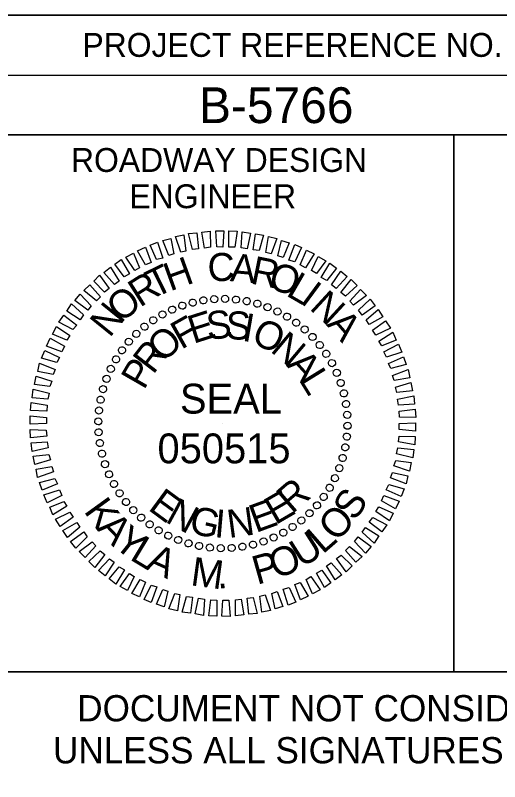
# Model space of a CAD drawing. Extents: x 573078 to 573131.9, y -55221.3 to -55195.5.
# Drawn here: x 573107.676 to 573109.706, y -55203.009 to -55199.798 of the extents above; entities that cross this region are included whole.
import ezdxf

# ---------------------------------------------------------------- set-up
doc = ezdxf.new("R2010")
doc.units = 0
for name, color, linetype in [('Prop Dimension', 7, 'Continuous'), ('Scratch_Level_1', 7, 'Continuous'), ('Sheet Data Field CELL', 7, 'Continuous'), ('Sheet Profile CELL', 7, 'Continuous'), ('Sheet Sticker Exception Certification CELL', 7, 'Continuous')]:
    doc.layers.add(name, color=color, linetype=linetype)

msp = doc.modelspace()

# ---------------------------------------------------------------- linework, layer by layer
at = {"layer": 'Prop Dimension'}
for p, q in [((573108.3752, -55201.0139), (573108.3752, -55201.0139)), ((573108.419, -55201.0014), (573108.419, -55201.0014)), ((573108.4648, -55200.9931), (573108.4648, -55200.9931)), ((573108.5094, -55200.9869), (573108.5094, -55200.9869)), ((573108.5553, -55200.9859), (573108.5553, -55200.9859)), ((573108.6011, -55200.9889), (573108.6011, -55200.9889)), ((573108.646, -55200.9964), (573108.646, -55200.9964)), ((573108.6897, -55201.0056), (573108.6897, -55201.0056)), ((573108.3336, -55201.0306), (573108.3336, -55201.0306)), ((573108.7335, -55201.0202), (573108.7335, -55201.0202)), ((573108.7751, -55201.0389), (573108.7751, -55201.0389)), ((573108.2533, -55201.0755), (573108.2533, -55201.0755)), ((573108.2928, -55201.0514), (573108.2928, -55201.0514)), ((573108.8156, -55201.0598), (573108.8156, -55201.0598)), ((573108.2169, -55201.1014), (573108.2169, -55201.1014)), ((573108.8531, -55201.0859), (573108.8531, -55201.0859)), ((573108.1825, -55201.1327), (573108.1825, -55201.1327)), ((573108.8897, -55201.1139), (573108.8897, -55201.1139)), ((573108.1512, -55201.1651), (573108.1512, -55201.1651)), ((573108.9218, -55201.1452), (573108.9218, -55201.1452)), ((573108.1232, -55201.2014), (573108.1232, -55201.2014)), ((573108.9531, -55201.1796), (573108.9531, -55201.1796)), ((573108.0971, -55201.2389), (573108.0971, -55201.2389)), ((573108.9792, -55201.216), (573108.9792, -55201.216)), ((573109.0031, -55201.2555), (573109.0031, -55201.2555)), ((573108.0762, -55201.2796), (573108.0762, -55201.2796)), ((573109.0239, -55201.2963), (573109.0239, -55201.2963)), ((573108.0575, -55201.3213), (573108.0575, -55201.3213)), ((573108.0429, -55201.365), (573108.0429, -55201.365)), ((573109.0405, -55201.3379), (573109.0405, -55201.3379)), ((573109.053, -55201.3817), (573109.053, -55201.3817)), ((573108.0337, -55201.4087), (573108.0337, -55201.4087)), ((573109.0614, -55201.4275), (573109.0614, -55201.4275)), ((573108.0262, -55201.4534), (573108.0262, -55201.4534)), ((573109.0676, -55201.4721), (573109.0676, -55201.4721)), ((573108.0232, -55201.4992), (573108.0232, -55201.4992)), ((573108.546, -55201.5087), (573108.546, -55201.5087)), ((573109.0688, -55201.518), (573109.0688, -55201.518)), ((573108.0242, -55201.545), (573108.0242, -55201.545)), ((573108.0304, -55201.5899), (573108.0304, -55201.5899)), ((573109.0655, -55201.5638), (573109.0655, -55201.5638)), ((573109.0584, -55201.6087), (573109.0584, -55201.6087)), ((573108.0387, -55201.6358), (573108.0387, -55201.6358)), ((573109.0489, -55201.6524), (573109.0489, -55201.6524)), ((573108.0512, -55201.6795), (573108.0512, -55201.6795)), ((573108.0679, -55201.7211), (573108.0679, -55201.7211)), ((573109.0343, -55201.6962), (573109.0343, -55201.6962)), ((573109.0156, -55201.7378), (573109.0156, -55201.7378)), ((573108.0887, -55201.7616), (573108.0887, -55201.7616)), ((573108.9947, -55201.7783), (573108.9947, -55201.7783)), ((573108.1128, -55201.8012), (573108.1128, -55201.8012)), ((573108.9688, -55201.8158), (573108.9688, -55201.8158)), ((573108.1387, -55201.8378), (573108.1387, -55201.8378)), ((573108.17, -55201.872), (573108.17, -55201.872)), ((573108.9406, -55201.8524), (573108.9406, -55201.8524)), ((573108.2024, -55201.9033), (573108.2024, -55201.9033)), ((573108.9093, -55201.8845), (573108.9093, -55201.8845)), ((573108.2387, -55201.9315), (573108.2387, -55201.9315)), ((573108.8385, -55201.9419), (573108.8385, -55201.9419)), ((573108.8751, -55201.9158), (573108.8751, -55201.9158)), ((573108.2762, -55201.9574), (573108.2762, -55201.9574)), ((573108.3169, -55201.9783), (573108.3169, -55201.9783)), ((573108.7989, -55201.9658), (573108.7989, -55201.9658)), ((573108.3586, -55201.997), (573108.3586, -55201.997)), ((573108.7168, -55202.0032), (573108.7168, -55202.0032)), ((573108.7584, -55201.9866), (573108.7584, -55201.9866)), ((573108.4023, -55202.0116), (573108.4023, -55202.0116)), ((573108.446, -55202.0211), (573108.446, -55202.0211)), ((573108.4907, -55202.0282), (573108.4907, -55202.0282)), ((573108.5365, -55202.0315), (573108.5365, -55202.0315)), ((573108.5823, -55202.0303), (573108.5823, -55202.0303)), ((573108.6272, -55202.0241), (573108.6272, -55202.0241)), ((573108.6731, -55202.0157), (573108.6731, -55202.0157))]:
    msp.add_line(p, q, dxfattribs=at)
for points in [[(573108.369, -55200.7911), (573108.347, -55200.7256), (573108.3824, -55200.7182), (573108.3907, -55200.786)], [(573108.419, -55200.7797), (573108.4023, -55200.7131), (573108.4365, -55200.7099), (573108.444, -55200.7765)], [(573108.4689, -55200.7735), (573108.4574, -55200.7068), (573108.4928, -55200.7027), (573108.4939, -55200.7703)], [(573108.521, -55200.7682), (573108.5157, -55200.7006), (573108.5502, -55200.7015), (573108.546, -55200.7693)], [(573108.571, -55200.7693), (573108.571, -55200.7015), (573108.6053, -55200.7027), (573108.596, -55200.7703)], [(573108.6231, -55200.7723), (573108.6272, -55200.7048), (573108.6615, -55200.711), (573108.6481, -55200.7765)], [(573108.6731, -55200.7807), (573108.6823, -55200.714), (573108.7168, -55200.7193), (573108.6981, -55200.7839)], [(573108.7261, -55200.7922), (573108.7365, -55200.7244), (573108.7719, -55200.7328), (573108.748, -55200.7973)], [(573108.2678, -55200.8214), (573108.2408, -55200.761), (573108.272, -55200.7485), (573108.294, -55200.8152)], [(573108.319, -55200.8047), (573108.2949, -55200.7423), (573108.3273, -55200.7328), (573108.3407, -55200.7973)], [(573108.776, -55200.8057), (573108.7918, -55200.7411), (573108.8239, -55200.7515), (573108.798, -55200.8131)], [(573108.823, -55200.8244), (573108.8468, -55200.7589), (573108.876, -55200.7714), (573108.8469, -55200.8318)], [(573108.222, -55200.8432), (573108.1887, -55200.7848), (573108.2211, -55200.7703), (573108.2449, -55200.8339)], [(573108.8698, -55200.8443), (573108.8959, -55200.7828), (573108.9281, -55200.7973), (573108.8927, -55200.8557)], [(573108.1315, -55200.8943), (573108.0929, -55200.8411), (573108.12, -55200.8214), (573108.1544, -55200.8818)], [(573108.1774, -55200.8681), (573108.1387, -55200.8119), (573108.1711, -55200.7953), (573108.197, -55200.8557)], [(573108.9177, -55200.8681), (573108.9459, -55200.8089), (573108.9771, -55200.8265), (573108.9376, -55200.8806)], [(573108.092, -55200.9255), (573108.0471, -55200.8756), (573108.0753, -55200.8536), (573108.1116, -55200.9119)], [(573108.9584, -55200.8964), (573108.9947, -55200.836), (573109.0218, -55200.8577), (573108.9813, -55200.9089)], [(573108.0503, -55200.9577), (573108.0045, -55200.9119), (573108.0295, -55200.8869), (573108.07, -55200.9431)], [(573109.001, -55200.9276), (573109.0396, -55200.8702), (573109.0667, -55200.8931), (573109.0209, -55200.9422)], [(573109.0405, -55200.9598), (573109.0834, -55200.9056), (573109.1084, -55200.9306), (573109.0604, -55200.9755)], [(573108.0158, -55200.9943), (573107.9628, -55200.9515), (573107.9888, -55200.9276), (573108.0325, -55200.9776)], [(573109.078, -55200.9964), (573109.1229, -55200.9473), (573109.1479, -55200.9723), (573109.0938, -55201.013)], [(573107.9795, -55201.0338), (573107.9253, -55200.9931), (573107.9483, -55200.966), (573107.9941, -55201.0151)], [(573107.9483, -55201.0734), (573107.892, -55201.038), (573107.9117, -55201.0077), (573107.9617, -55201.0535)], [(573109.1146, -55201.0338), (573109.1625, -55200.9869), (573109.1843, -55201.0151), (573109.1292, -55201.0547)], [(573109.1458, -55201.0743), (573109.1968, -55201.0306), (573109.2167, -55201.0609), (573109.1583, -55201.0942)], [(573107.917, -55201.1151), (573107.8587, -55201.0838), (573107.8795, -55201.0547), (573107.9337, -55201.0963)], [(573109.1729, -55201.1172), (573109.228, -55201.0776), (573109.2479, -55201.1088), (573109.1875, -55201.138)], [(573107.892, -55201.1597), (573107.8325, -55201.1338), (573107.8483, -55201.1014), (573107.9045, -55201.1401)], [(573109.2, -55201.163), (573109.2583, -55201.1264), (573109.2717, -55201.1588), (573109.2125, -55201.1826)], [(573107.8712, -55201.2076), (573107.8066, -55201.1838), (573107.8221, -55201.1514), (573107.8816, -55201.1847)], [(573109.2208, -55201.2076), (573109.2821, -55201.1764), (573109.2958, -55201.2097), (573109.2312, -55201.2305)], [(573107.8504, -55201.2535), (573107.7858, -55201.2347), (573107.7992, -55201.2025), (573107.8617, -55201.2317)], [(573109.2396, -55201.2567), (573109.303, -55201.2296), (573109.3145, -55201.2618), (573109.25, -55201.2784)], [(573107.8346, -55201.3034), (573107.7701, -55201.29), (573107.7775, -55201.2555), (573107.843, -55201.2817)], [(573109.2562, -55201.3067), (573109.3229, -55201.2826), (573109.3291, -55201.3171), (573109.2634, -55201.3284)], [(573107.8212, -55201.3534), (573107.7566, -55201.3451), (573107.7638, -55201.3097), (573107.8295, -55201.3317)], [(573109.2687, -55201.3567), (573109.3342, -55201.3368), (573109.3405, -55201.3722), (573109.275, -55201.3784)], [(573107.8129, -55201.4067), (573107.7462, -55201.4004), (573107.7504, -55201.365), (573107.818, -55201.3817)], [(573109.278, -55201.4067), (573109.3458, -55201.3921), (573109.3488, -55201.4275), (573109.2821, -55201.4316)], [(573107.8076, -55201.4566), (573107.74, -55201.4546), (573107.7421, -55201.4201), (573107.8096, -55201.4316)], [(573109.2842, -55201.4566), (573109.352, -55201.4483), (573109.3541, -55201.4837), (573109.2863, -55201.4816)], [(573107.8066, -55201.5087), (573107.7388, -55201.5117), (573107.7388, -55201.4763), (573107.8066, -55201.4837)], [(573109.2854, -55201.5087), (573109.353, -55201.5055), (573109.353, -55201.5409), (573109.2854, -55201.5337)], [(573107.8076, -55201.5608), (573107.74, -55201.5691), (573107.7379, -55201.5337), (573107.8055, -55201.5358)], [(573109.2842, -55201.5608), (573109.352, -55201.5629), (573109.35, -55201.5971), (573109.2821, -55201.5858)], [(573107.8138, -55201.6108), (573107.7462, -55201.6253), (573107.743, -55201.5899), (573107.8096, -55201.5858)], [(573109.2791, -55201.6108), (573109.3458, -55201.617), (573109.3416, -55201.6524), (573109.2738, -55201.6358)], [(573107.8233, -55201.6607), (573107.7576, -55201.6804), (573107.7513, -55201.645), (573107.817, -55201.6388)], [(573107.8358, -55201.7107), (573107.7691, -55201.7346), (573107.7629, -55201.7003), (573107.8284, -55201.6888)], [(573109.2708, -55201.6638), (573109.3354, -55201.6721), (573109.328, -55201.7075), (573109.2625, -55201.6857)], [(573109.2572, -55201.7137), (573109.3217, -55201.7274), (573109.3145, -55201.7616), (573109.2488, -55201.7357)], [(573107.8524, -55201.7607), (573107.7888, -55201.7878), (573107.7775, -55201.7554), (573107.842, -55201.7387)], [(573109.2416, -55201.7637), (573109.3062, -55201.7825), (573109.2926, -55201.8149), (573109.2301, -55201.7857)], [(573107.8712, -55201.8096), (573107.8096, -55201.8408), (573107.7962, -55201.8075), (573107.8608, -55201.7866)], [(573109.2208, -55201.8095), (573109.2854, -55201.8336), (573109.2696, -55201.8658), (573109.2104, -55201.8325)], [(573107.892, -55201.8544), (573107.8337, -55201.8908), (573107.8201, -55201.8586), (573107.8795, -55201.8345)], [(573107.9191, -55201.9003), (573107.8638, -55201.9398), (573107.8441, -55201.9086), (573107.9045, -55201.8794)], [(573109.2, -55201.8575), (573109.2592, -55201.8836), (573109.2437, -55201.9158), (573109.1875, -55201.8774)], [(573109.175, -55201.9023), (573109.2333, -55201.9336), (573109.2125, -55201.9628), (573109.1583, -55201.9211)], [(573107.9462, -55201.9428), (573107.895, -55201.9866), (573107.8754, -55201.9565), (573107.9337, -55201.9232)], [(573109.1438, -55201.944), (573109.2, -55201.9794), (573109.1801, -55202.0095), (573109.1301, -55201.9637)], [(573107.9774, -55201.9836), (573107.9295, -55202.0303), (573107.9075, -55202.0023), (573107.9628, -55201.9628)], [(573108.0137, -55202.0211), (573107.9691, -55202.0699), (573107.9441, -55202.0449), (573107.9982, -55202.0044)], [(573109.1125, -55201.9836), (573109.1667, -55202.0241), (573109.1438, -55202.0512), (573109.0979, -55202.0023)], [(573108.0512, -55202.0574), (573108.0087, -55202.1116), (573107.9837, -55202.0866), (573108.0316, -55202.0419)], [(573109.076, -55202.0231), (573109.1292, -55202.0657), (573109.103, -55202.0898), (573109.0593, -55202.0398)], [(573108.0908, -55202.0898), (573108.0524, -55202.147), (573108.0253, -55202.124), (573108.0711, -55202.0752)], [(573109.0417, -55202.0595), (573109.0875, -55202.1053), (573109.0625, -55202.1303), (573109.0218, -55202.0741)], [(573109.0001, -55202.0919), (573109.0447, -55202.1419), (573109.0167, -55202.1636), (573108.9801, -55202.1053)], [(573108.1336, -55202.121), (573108.0971, -55202.1814), (573108.07, -55202.1595), (573108.1107, -55202.1085)], [(573108.1741, -55202.149), (573108.1461, -55202.2085), (573108.1149, -55202.1907), (573108.1544, -55202.1365)], [(573108.9605, -55202.1231), (573108.9989, -55202.1761), (573108.9718, -55202.196), (573108.9376, -55202.1356)], [(573108.222, -55202.1731), (573108.1961, -55202.2344), (573108.1637, -55202.2199), (573108.1991, -55202.1615)], [(573108.9147, -55202.149), (573108.9531, -55202.2053), (573108.9209, -55202.2219), (573108.8948, -55202.1615)], [(573108.269, -55202.1928), (573108.2449, -55202.2585), (573108.2158, -55202.246), (573108.2449, -55202.1856)], [(573108.8239, -55202.196), (573108.851, -55202.2564), (573108.8198, -55202.2689), (573108.798, -55202.2023)], [(573108.8698, -55202.174), (573108.9031, -55202.2323), (573108.8709, -55202.2469), (573108.8468, -55202.1835)], [(573108.3158, -55202.2115), (573108.3002, -55202.2761), (573108.2678, -55202.2657), (573108.294, -55202.2044)], [(573108.3657, -55202.2252), (573108.3553, -55202.2927), (573108.3199, -55202.2844), (573108.344, -55202.2199)], [(573108.419, -55202.2365), (573108.4095, -55202.3032), (573108.3752, -55202.2981), (573108.394, -55202.2335)], [(573108.723, -55202.2261), (573108.7448, -55202.2918), (573108.7094, -55202.299), (573108.7011, -55202.2314)], [(573108.773, -55202.2127), (573108.7969, -55202.2752), (573108.7647, -55202.2844), (573108.751, -55202.2199)], [(573108.4689, -55202.2448), (573108.4648, -55202.3127), (573108.4303, -55202.3064), (573108.444, -55202.2407)], [(573108.521, -55202.2481), (573108.521, -55202.3157), (573108.4865, -55202.3147), (573108.496, -55202.2469)], [(573108.571, -55202.249), (573108.5761, -55202.3168), (573108.5418, -55202.3157), (573108.546, -55202.2481)], [(573108.6231, -55202.2439), (573108.6344, -55202.3106), (573108.599, -55202.3147), (573108.5981, -55202.2469)], [(573108.6731, -55202.2377), (573108.6897, -55202.3043), (573108.6552, -55202.3073), (573108.6481, -55202.2407)]]:
    msp.add_lwpolyline(points, close=True, dxfattribs=at)
for centre, major_axis in [((573108.4643, -55200.9927), (-0.0023, 0.0148)), ((573108.5096, -55200.9876), (-0.001, 0.015)), ((573108.5551, -55200.9864), (0.0003, 0.015)), ((573108.6006, -55200.9892), (0.0016, 0.0149)), ((573108.6457, -55200.9959), (0.0029, 0.0147)), ((573108.3336, -55201.0315), (-0.0061, 0.0137)), ((573108.376, -55201.0147), (-0.0049, 0.0142)), ((573108.4196, -55201.0018), (-0.0036, 0.0146)), ((573108.69, -55201.0065), (0.0041, 0.0144)), ((573108.7332, -55201.021), (0.0054, 0.014)), ((573108.2928, -55201.0518), (-0.0073, 0.0131)), ((573108.775, -55201.0392), (0.0066, 0.0135)), ((573108.8151, -55201.0609), (0.0077, 0.0129)), ((573108.2539, -55201.0756), (-0.0084, 0.0124)), ((573108.8531, -55201.0861), (0.0088, 0.0121)), ((573108.2173, -55201.1027), (-0.0094, 0.0117)), ((573108.8887, -55201.1144), (0.0098, 0.0113)), ((573108.1832, -55201.1329), (-0.0104, 0.0108)), ((573108.9218, -55201.1458), (0.0108, 0.0104)), ((573108.1518, -55201.1659), (-0.0113, 0.0098)), ((573108.952, -55201.1799), (0.0117, 0.0094)), ((573108.1234, -55201.2016), (-0.0121, 0.0088)), ((573108.9791, -55201.2165), (0.0124, 0.0084)), ((573108.0983, -55201.2396), (-0.0129, 0.0077)), ((573109.0029, -55201.2554), (0.0131, 0.0073)), ((573108.0765, -55201.2797), (-0.0135, 0.0066)), ((573108.0584, -55201.3214), (-0.014, 0.0054)), ((573109.0232, -55201.2962), (0.0137, 0.0061)), ((573109.0399, -55201.3386), (0.0142, 0.0049)), ((573108.0439, -55201.3647), (-0.0144, 0.0041)), ((573109.0529, -55201.3823), (0.0146, 0.0036)), ((573108.0333, -55201.409), (-0.0147, 0.0029)), ((573109.0619, -55201.4269), (0.0148, 0.0023)), ((573108.0265, -55201.454), (-0.0149, 0.0016)), ((573109.0671, -55201.4722), (0.015, 0.001)), ((573108.0237, -55201.4995), (-0.015, 0.0003)), ((573108.0249, -55201.5451), (-0.015, -0.001)), ((573109.0683, -55201.5178), (0.015, -0.0003)), ((573109.0655, -55201.5632), (0.0149, -0.0016)), ((573108.0301, -55201.5904), (-0.0148, -0.0023)), ((573109.0588, -55201.6083), (0.0147, -0.0029)), ((573108.0392, -55201.635), (-0.0146, -0.0036)), ((573109.0481, -55201.6526), (0.0144, -0.0041)), ((573108.0521, -55201.6787), (-0.0142, -0.0049)), ((573109.0337, -55201.6958), (0.014, -0.0054)), ((573108.0688, -55201.7211), (-0.0137, -0.0061)), ((573109.0155, -55201.7376), (0.0135, -0.0066)), ((573108.0892, -55201.7619), (-0.0131, -0.0073)), ((573108.113, -55201.8007), (-0.0124, -0.0084)), ((573108.9938, -55201.7777), (0.0129, -0.0077)), ((573108.9686, -55201.8157), (0.0121, -0.0088)), ((573108.1401, -55201.8374), (-0.0117, -0.0094)), ((573108.9402, -55201.8513), (0.0113, -0.0098)), ((573108.1703, -55201.8715), (-0.0108, -0.0104)), ((573108.9089, -55201.8844), (0.0104, -0.0108)), ((573108.2033, -55201.9029), (-0.0098, -0.0113)), ((573108.239, -55201.9312), (-0.0088, -0.0121)), ((573108.8747, -55201.9146), (0.0094, -0.0117)), ((573108.277, -55201.9564), (-0.0077, -0.0129)), ((573108.8381, -55201.9417), (0.0084, -0.0124)), ((573108.317, -55201.9781), (-0.0066, -0.0135)), ((573108.7585, -55201.9858), (0.0061, -0.0137)), ((573108.7993, -55201.9655), (0.0073, -0.0131)), ((573108.3588, -55201.9963), (-0.0054, -0.014)), ((573108.402, -55202.0108), (-0.0041, -0.0144)), ((573108.4463, -55202.0214), (-0.0029, -0.0147)), ((573108.6277, -55202.0246), (0.0023, -0.0148)), ((573108.6724, -55202.0155), (0.0036, -0.0146)), ((573108.7161, -55202.0025), (0.0049, -0.0142)), ((573108.4914, -55202.0281), (-0.0016, -0.0149)), ((573108.5369, -55202.0309), (-0.0003, -0.015)), ((573108.5825, -55202.0297), (0.001, -0.015))]:
    msp.add_ellipse(centre, major_axis=major_axis, ratio=0.999708, dxfattribs=at)
at = {"layer": 'Scratch_Level_1'}
msp.add_line((573108.546, -55201.5087), (573108.546, -55201.5087), dxfattribs=at)
at = {"layer": 'Sheet Profile CELL'}
for p, q in [((573107.5142, -55200.0494), (573111.5142, -55200.0494)), ((573109.5142, -55200.2994), (573109.5142, -55202.5484))]:
    msp.add_line(p, q, dxfattribs=at)
for points in [[(573111.5142, -55199.7984), (573081.5142, -55199.7984), (573081.5142, -55220.7984), (573111.5142, -55220.7984)], [(573107.5142, -55199.7984), (573111.5142, -55199.7984), (573111.5142, -55200.2994), (573107.5142, -55200.2994)], [(573107.5142, -55200.2994), (573109.5142, -55200.2994), (573109.5142, -55202.5494), (573107.5142, -55202.5494)], [(573109.5142, -55200.2994), (573111.5142, -55200.2994), (573111.5142, -55202.5494), (573109.5142, -55202.5494)]]:
    msp.add_lwpolyline(points, close=True, dxfattribs=at)
at = {"layer": 'Sheet Sticker Exception Certification CELL'}
msp.add_line((573107.5142, -55202.5494), (573111.5149, -55202.5494), dxfattribs=at)

# ---------------------------------------------------------------- texts
at = {"layer": 'Prop Dimension'}
for s, height, rotation, p in [('H', 0.1177, 19.8207, (573108.3243, -55200.9554)), ('C', 0.1177, 1.0718, (573108.4826, -55200.9128)), ('A', 0.1177, 354.8222, (573108.5742, -55200.9117)), ('R', 0.1177, 348.5725, (573108.6576, -55200.9211)), ('T', 0.1177, 26.0703, (573108.2609, -55200.9846)), ('O', 0.1177, 342.3229, (573108.7304, -55200.9399)), ('R', 0.1177, 32.3199, (573108.1984, -55201.0241)), ('L', 0.1177, 329.8237, (573108.8066, -55200.97)), ('I', 0.1177, 323.5741, (573108.8649, -55201.0003)), ('O', 0.1177, 38.5695, (573108.1181, -55201.0898)), ('N', 0.1177, 317.3244, (573108.9054, -55201.0274)), ('N', 0.1177, 51.0688, (573108.0714, -55201.1523)), ('E', 0.1177, 17.6709, (573108.4222, -55201.1752)), ('S', 0.1177, 6.1833, (573108.4826, -55201.1586)), ('S', 0.1177, 358.4778, (573108.5567, -55201.1553)), ('I', 0.1177, 350.0931, (573108.6233, -55201.1607)), ('F', 0.1177, 29.3, (573108.3713, -55201.2002)), ('O', 0.1177, 335.3611, (573108.6596, -55201.1678)), ('A', 0.1177, 311.0748, (573108.9774, -55201.0949)), ('O', 0.1177, 43.5875, (573108.2972, -55201.2565)), ('N', 0.1177, 319.95, (573108.7409, -55201.2044)), ('R', 0.1177, 52.4166, (573108.2535, -55201.3065)), ('P', 0.1177, 60.1222, (573108.2151, -55201.371)), ('A', 0.1177, 312.2445, (573108.8096, -55201.2657)), ('L', 0.1177, 301.6752, (573108.8617, -55201.324)), ('SEAL', 0.12497, 360, (573108.366, -55201.4668)), ('050515', 0.12497, 360, (573108.2719, -55201.6751)), ('R', 0.1177, 40.7353, (573108.8357, -55201.8896)), ('E', 0.1177, 323.6798, (573108.2285, -55201.8676)), ('E', 0.1177, 30.1214, (573108.7659, -55201.9354)), ('S', 0.12, 57.1863, (573109.1004, -55201.921)), ('K', 0.12, 305.9043, (573107.9606, -55201.8757)), ('N', 0.1177, 331.3854, (573108.3005, -55201.9188)), ('E', 0.1177, 20.0411, (573108.6837, -55201.9676)), ('G', 0.1177, 346.7965, (573108.3993, -55201.9646)), ('I', 0.1177, 355.0405, (573108.5076, -55201.9843)), ('N', 0.1177, 7.7341, (573108.5712, -55201.9884)), ('O', 0.12, 47.4888, (573109.0231, -55202.0085)), ('A', 0.12, 313.5599, (573108.0147, -55201.9504)), ('Y', 0.12, 321.5623, (573108.0814, -55202.0201)), ('U', 0.12, 32.399, (573108.8765, -55202.1155)), ('L', 0.12, 41.0852, (573108.9643, -55202.0586)), ('L', 0.12, 328.9868, (573108.1513, -55202.0758)), ('A', 0.12, 335.3904, (573108.2171, -55202.1163)), ('O', 0.12, 22.7015, (573108.7696, -55202.1625)), ('M', 0.12, 352.2427, (573108.4073, -55202.1856)), ('P', 0.12, 15.7778, (573108.6891, -55202.1846)), ('.', 0.12, 1.9209, (573108.5231, -55202.1992))]:
    msp.add_text(s, height=height, rotation=rotation, dxfattribs=at).set_placement(p)
at = {"layer": 'Sheet Data Field CELL'}
msp.add_text('B-5766', height=0.15, dxfattribs=at).set_placement((573108.4462, -55200.2499))
at = {"layer": 'Sheet Profile CELL'}
for s, height, p in [('PROJECT REFERENCE NO.', 0.100002, (573107.9572, -55199.9724)), ('ROADWAY DESIGN', 0.100002, (573107.9092, -55200.4544)), ('ENGINEER', 0.1, (573108.1542, -55200.6064))]:
    msp.add_text(s, height=height, dxfattribs=at).set_placement(p)
at = {"layer": 'Sheet Sticker Exception Certification CELL'}
for s, p in [('DOCUMENT NOT CONSIDERED FINAL', (573107.9356, -55202.7563)), ('UNLESS ALL SIGNATURES COMPLETED', (573107.8342, -55202.9323))]:
    msp.add_text(s, height=0.11, dxfattribs=at).set_placement(p)

doc.saveas('drawing.dxf')
